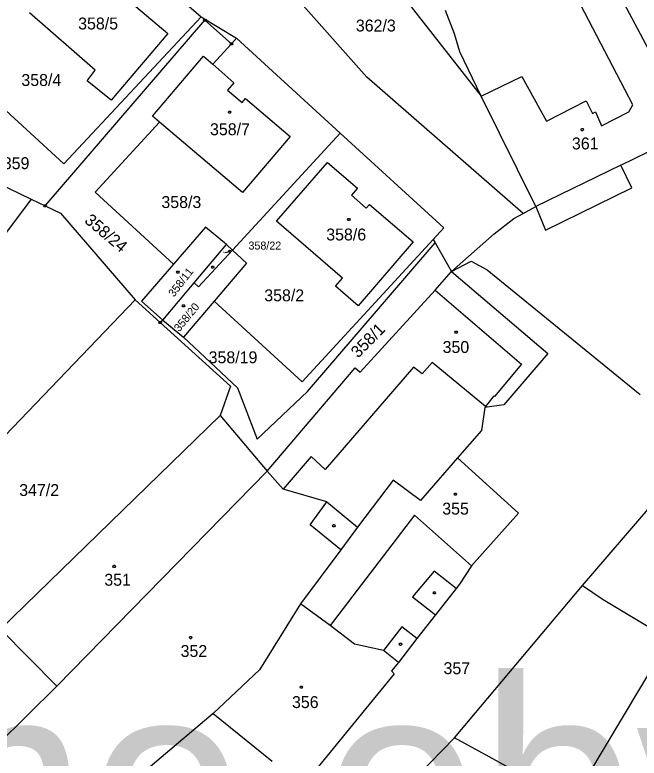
# Model space of a CAD drawing. Extents: x -634640 to -629202, y -1196156 to -1190068.
# Drawn here: x -631895.1 to -631806.2, y -1192622.8 to -1192516.9 of the extents above; entities that cross this region are included whole.
import ezdxf

# ---------------------------------------------------------------- set-up
doc = ezdxf.new("R2010")
doc.units = 0
for name, color, linetype in [('Obvod šetřený', 7, 'Continuous'), ('Vrstva 1', 7, 'Continuous'), ('Vrstva 2', 7, 'Continuous'), ('Vrstva 3', 7, 'Continuous'), ('Vrstva 4', 7, 'Continuous'), ('Vrstva 5', 7, 'Continuous'), ('Vrstva 7', 7, 'Continuous'), ('Vrstva 8', 7, 'Continuous')]:
    doc.layers.add(name, color=color, linetype=linetype)

msp = doc.modelspace()

# ---------------------------------------------------------------- linework, layer by layer
at = {"layer": 'Vrstva 1'}
for p, q in [((-631848.47, -1192503.23), (-631828.68, -1192528.47)), ((-631883.69, -1192504.04), (-631868.59, -1192517.16)), ((-631809.06, -1192513.86), (-631802.3, -1192526.65)), ((-631879.64, -1192514.17), (-631873.34, -1192519.53)), ((-631854.05, -1192515.52), (-631844.97, -1192525.74)), ((-631883.7, -1192524.73), (-631893.04, -1192516.58)), ((-631832.49, -1192519.55), (-631833.8, -1192516.26)), ((-631890.82, -1192544.07), (-631868.06, -1192517.61)), ((-631888.14, -1192538.1), (-631868.59, -1192517.16)), ((-631868.59, -1192517.16), (-631863.55, -1192520.21)), ((-631868.06, -1192517.61), (-631864.27, -1192521)), ((-631873.34, -1192519.53), (-631881.41, -1192529.02)), ((-631864.27, -1192521), (-631863.55, -1192520.21)), ((-631849.92, -1192532.66), (-631863.55, -1192520.21)), ((-631831.75, -1192522.13), (-631832.49, -1192519.55)), ((-631866.95, -1192523.91), (-631864.27, -1192521)), ((-631828.68, -1192528.47), (-631831.75, -1192522.13)), ((-631875.53, -1192531.28), (-631868.28, -1192522.74)), ((-631868.28, -1192522.74), (-631866.95, -1192523.91)), ((-631866.95, -1192523.91), (-631863.93, -1192526.55)), ((-631884.83, -1192526.29), (-631883.7, -1192524.73)), ((-631881.41, -1192529.02), (-631884.83, -1192526.29)), ((-631863.93, -1192526.55), (-631864.82, -1192527.6)), ((-631822.7, -1192545.15), (-631844.97, -1192525.74)), ((-631864.82, -1192527.6), (-631862.75, -1192529.35)), ((-631888.14, -1192538.1), (-631898.97, -1192528.19)), ((-631820.89, -1192544.18), (-631828.68, -1192528.47)), ((-631862.75, -1192529.35), (-631862.27, -1192528.79)), ((-631862.27, -1192528.79), (-631855.91, -1192534.19)), ((-631874.52, -1192532.14), (-631875.53, -1192531.28)), ((-631883.71, -1192542.15), (-631874.52, -1192532.14)), ((-631862.72, -1192542.16), (-631874.52, -1192532.14)), ((-631848.78, -1192533.71), (-631849.92, -1192532.66)), ((-631848.78, -1192533.71), (-631864.13, -1192550.4)), ((-631848.78, -1192533.71), (-631834.02, -1192547.2)), ((-631855.91, -1192534.19), (-631862.72, -1192542.16)), ((-631808.78, -1192538.27), (-631804.91, -1192536.38)), ((-631903.73, -1192537.87), (-631892.82, -1192543.11)), ((-631857.88, -1192546.27), (-631850.61, -1192537.89)), ((-631850.61, -1192537.89), (-631846.32, -1192541.58)), ((-631807.24, -1192541.51), (-631808.78, -1192538.27)), ((-631872.52, -1192552.38), (-631883.71, -1192542.15)), ((-631846.32, -1192541.58), (-631847.19, -1192542.57)), ((-631819.52, -1192547.54), (-631807.24, -1192541.51)), ((-631892.82, -1192543.11), (-631924.11, -1192584.85)), ((-631892.82, -1192543.11), (-631890.82, -1192544.07)), ((-631847.19, -1192542.57), (-631845.08, -1192544.43)), ((-631890.82, -1192544.07), (-631888.62, -1192545.13)), ((-631845.08, -1192544.43), (-631844.61, -1192543.9)), ((-631844.61, -1192543.9), (-631838.38, -1192549.21)), ((-631822.7, -1192545.15), (-631820.89, -1192544.18)), ((-631820.89, -1192544.18), (-631819.52, -1192547.54)), ((-631888.62, -1192545.13), (-631877.99, -1192557.46)), ((-631824.05, -1192545.87), (-631822.7, -1192545.15)), ((-631848.46, -1192554.39), (-631857.88, -1192546.27)), ((-631826.84, -1192548.08), (-631824.05, -1192545.87)), ((-631834.02, -1192547.2), (-631835.55, -1192548.86)), ((-631832.9, -1192553.43), (-631826.84, -1192548.08)), ((-631869.59, -1192555.06), (-631864.98, -1192549.6)), ((-631864.98, -1192549.6), (-631864.13, -1192550.4)), ((-631835.55, -1192548.86), (-631854.19, -1192569.14)), ((-631838.38, -1192549.21), (-631846.23, -1192558.32)), ((-631835.55, -1192548.86), (-631835.27, -1192549.34)), ((-631835.27, -1192549.34), (-631832.9, -1192553.43)), ((-631864.13, -1192550.4), (-631868.95, -1192555.64)), ((-631832.9, -1192553.43), (-631830.13, -1192551.98)), ((-631830.13, -1192551.98), (-631827.83, -1192553.2)), ((-631835.24, -1192556.11), (-631832.9, -1192553.43)), ((-631832.9, -1192553.43), (-631819.2, -1192565.12)), ((-631827.83, -1192553.2), (-631806.05, -1192570.95)), ((-631874.07, -1192560.35), (-631869.59, -1192555.06)), ((-631868.95, -1192555.64), (-631869.59, -1192555.06)), ((-631849.45, -1192555.54), (-631848.46, -1192554.39)), ((-631846.23, -1192558.32), (-631849.45, -1192555.54)), ((-631845.93, -1192567.79), (-631835.24, -1192556.11)), ((-631917.12, -1192598.24), (-631877.99, -1192557.46)), ((-631877.99, -1192557.46), (-631874.44, -1192560.69)), ((-631866.74, -1192557.66), (-631871.11, -1192562.8)), ((-631854.19, -1192569.14), (-631866.74, -1192557.66)), ((-631874.07, -1192560.35), (-631874.44, -1192560.69)), ((-631874.07, -1192560.35), (-631871.11, -1192562.8)), ((-631874.44, -1192560.69), (-631864.43, -1192569.77)), ((-631819.2, -1192565.12), (-631825.47, -1192572.45)), ((-631859.17, -1192581.88), (-631846.63, -1192567.18)), ((-631846.63, -1192567.18), (-631845.93, -1192567.79)), ((-631864.43, -1192569.77), (-631865.89, -1192573.94)), ((-631828.17, -1192572.8), (-631828.64, -1192576.1)), ((-631825.47, -1192572.45), (-631828.17, -1192572.8)), ((-631865.89, -1192573.94), (-631897.2, -1192604.41)), ((-631865.89, -1192573.94), (-631859.17, -1192581.88)), ((-631828.64, -1192576.1), (-631832.09, -1192579.98)), ((-631832.09, -1192579.98), (-631837.33, -1192586.04)), ((-631832.09, -1192579.98), (-631823.36, -1192587.86)), ((-631859.17, -1192581.88), (-631889.18, -1192612.51)), ((-631856.92, -1192584.46), (-631859.17, -1192581.88)), ((-631841.22, -1192583.17), (-631846.32, -1192589.87)), ((-631837.33, -1192586.04), (-631841.22, -1192583.17)), ((-631850.67, -1192586.25), (-631856.92, -1192584.46)), ((-631853.08, -1192589.54), (-631850.67, -1192586.25)), ((-631823.36, -1192587.86), (-631830.08, -1192595.38)), ((-631814.24, -1192598.16), (-631804.61, -1192586.97)), ((-631848.71, -1192593.08), (-631853.08, -1192589.54)), ((-631846.32, -1192589.87), (-631848.71, -1192593.08)), ((-631848.71, -1192593.08), (-631854.42, -1192600.76)), ((-631830.08, -1192595.38), (-631831.79, -1192597.99)), ((-631832.48, -1192619.85), (-631814.24, -1192598.16)), ((-631831.79, -1192597.99), (-631832.27, -1192598.6)), ((-631832.27, -1192598.6), (-631835.2, -1192602.35)), ((-631854.42, -1192600.76), (-631860.29, -1192610.17)), ((-631850.21, -1192603.87), (-631854.42, -1192600.76)), ((-631835.2, -1192602.35), (-631837.85, -1192605.74)), ((-631846.76, -1192606.54), (-631850.21, -1192603.87)), ((-631897.2, -1192604.41), (-631889.18, -1192612.51)), ((-631837.85, -1192605.74), (-631840.49, -1192609.12)), ((-631801.93, -1192605.84), (-631815.78, -1192629)), ((-631842.62, -1192607.45), (-631846.76, -1192606.54)), ((-631840.49, -1192609.12), (-631842.62, -1192607.45)), ((-631840.49, -1192609.12), (-631841.45, -1192610.33)), ((-631860.29, -1192610.17), (-631866.88, -1192616.39)), ((-631841.08, -1192610.76), (-631854.21, -1192626.77)), ((-631841.45, -1192610.33), (-631841.08, -1192610.76)), ((-631889.18, -1192612.51), (-631899.64, -1192622.83)), ((-631866.88, -1192616.39), (-631880.98, -1192628.29)), ((-631866.88, -1192616.39), (-631858.46, -1192623.18)), ((-631851.26, -1192639.1), (-631832.48, -1192619.85)), ((-631815.78, -1192629), (-631832.48, -1192619.85))]:
    msp.add_line(p, q, dxfattribs=at)
for points in [[(-631864.98, -1192549.6), (-631867.96, -1192547.12), (-631872.52, -1192552.38)], [(-631871.11, -1192562.8), (-631863.41, -1192570.03), (-631860.61, -1192577.31), (-631853.46, -1192570.55), (-631835.27, -1192549.34)], [(-631864.13, -1192550.4), (-631862.14, -1192552.25), (-631866.74, -1192557.66)], [(-631872.52, -1192552.38), (-631877.08, -1192557.66), (-631874.07, -1192560.35)]]:
    msp.add_lwpolyline(points, dxfattribs=at)
at = {"layer": 'Vrstva 3'}
for points in [[(-631880.91, -1192595.29), (-631880.82, -1192595.44), (-631880.91, -1192595.59), (-631881.09, -1192595.59), (-631881.18, -1192595.44), (-631881.09, -1192595.29), (-631880.91, -1192595.29)], [(-631870, -1192605.45), (-631869.91, -1192605.6), (-631870, -1192605.75), (-631870.18, -1192605.75), (-631870.27, -1192605.6), (-631870.18, -1192605.45), (-631870, -1192605.45)], [(-631854.24, -1192612.5), (-631854.15, -1192612.65), (-631854.24, -1192612.8), (-631854.42, -1192612.8), (-631854.51, -1192612.65), (-631854.42, -1192612.5), (-631854.24, -1192612.5)]]:
    msp.add_lwpolyline(points, dxfattribs=at)
at = {"layer": 'Vrstva 4'}
for p, q in [((-631807.1, -1192529.67), (-631822.2, -1192500.63)), ((-631828.68, -1192528.47), (-631822.89, -1192525.66)), ((-631822.89, -1192525.66), (-631819.41, -1192532.02)), ((-631819.41, -1192532.02), (-631813.73, -1192529.12)), ((-631813.73, -1192529.12), (-631812.83, -1192530.92)), ((-631807.64, -1192530.68), (-631807.1, -1192529.67)), ((-631812.83, -1192530.92), (-631812.4, -1192530.69)), ((-631812.4, -1192530.69), (-631811.53, -1192532.7)), ((-631811.53, -1192532.7), (-631807.64, -1192530.68)), ((-631808.78, -1192538.27), (-631820.89, -1192544.18)), ((-631835.24, -1192556.11), (-631822.95, -1192566.65)), ((-631835.7, -1192566.41), (-631837.1, -1192568)), ((-631828.07, -1192572.67), (-631835.7, -1192566.41)), ((-631822.95, -1192566.65), (-631826.78, -1192571.23)), ((-631838.34, -1192567.04), (-631850.91, -1192581.65)), ((-631837.1, -1192568), (-631838.34, -1192567.04)), ((-631826.89, -1192571.15), (-631828.07, -1192572.67)), ((-631826.78, -1192571.23), (-631826.89, -1192571.15)), ((-631852.93, -1192579.8), (-631856.92, -1192584.46)), ((-631850.91, -1192581.65), (-631852.93, -1192579.8)), ((-631850.67, -1192586.25), (-631846.32, -1192589.87)), ((-631838.2, -1192588.17), (-631850.21, -1192603.87)), ((-631830.08, -1192595.38), (-631838.2, -1192588.17)), ((-631835.41, -1192596.12), (-631838.46, -1192599.78)), ((-631832.27, -1192598.6), (-631835.41, -1192596.12)), ((-631814.24, -1192598.16), (-631811.3, -1192600.18)), ((-631838.46, -1192599.78), (-631835.2, -1192602.35)), ((-631811.3, -1192600.18), (-631804.41, -1192604.31)), ((-631839.98, -1192604.05), (-631842.62, -1192607.45)), ((-631837.85, -1192605.74), (-631839.98, -1192604.05))]:
    msp.add_line(p, q, dxfattribs=at)
at = {"layer": 'Vrstva 5'}
for points in [[(-631864.45, -1192530.57), (-631864.36, -1192530.72), (-631864.45, -1192530.87), (-631864.63, -1192530.87), (-631864.72, -1192530.72), (-631864.63, -1192530.57), (-631864.45, -1192530.57)], [(-631814.2, -1192533.07), (-631814.11, -1192533.22), (-631814.2, -1192533.37), (-631814.38, -1192533.37), (-631814.47, -1192533.22), (-631814.38, -1192533.07), (-631814.2, -1192533.07)], [(-631847.46, -1192545.89), (-631847.37, -1192546.04), (-631847.46, -1192546.19), (-631847.64, -1192546.19), (-631847.73, -1192546.04), (-631847.64, -1192545.89), (-631847.46, -1192545.89)], [(-631866.86, -1192552.65), (-631866.77, -1192552.8), (-631866.86, -1192552.95), (-631867.04, -1192552.95), (-631867.13, -1192552.8), (-631867.04, -1192552.65), (-631866.86, -1192552.65)], [(-631871.84, -1192553.39), (-631871.75, -1192553.54), (-631871.84, -1192553.69), (-631872.02, -1192553.69), (-631872.11, -1192553.54), (-631872.02, -1192553.39), (-631871.84, -1192553.39)], [(-631871.03, -1192558.17), (-631870.94, -1192558.32), (-631871.03, -1192558.47), (-631871.21, -1192558.47), (-631871.3, -1192558.32), (-631871.21, -1192558.17), (-631871.03, -1192558.17)], [(-631832.16, -1192561.92), (-631832.07, -1192562.07), (-631832.16, -1192562.22), (-631832.34, -1192562.22), (-631832.43, -1192562.07), (-631832.34, -1192561.92), (-631832.16, -1192561.92)], [(-631832.29, -1192585.02), (-631832.2, -1192585.17), (-631832.29, -1192585.32), (-631832.47, -1192585.32), (-631832.56, -1192585.17), (-631832.47, -1192585.02), (-631832.29, -1192585.02)], [(-631849.59, -1192589.5), (-631849.5, -1192589.65), (-631849.59, -1192589.8), (-631849.77, -1192589.8), (-631849.86, -1192589.65), (-631849.77, -1192589.5), (-631849.59, -1192589.5)], [(-631835.28, -1192599.07), (-631835.19, -1192599.22), (-631835.28, -1192599.37), (-631835.46, -1192599.37), (-631835.55, -1192599.22), (-631835.46, -1192599.07), (-631835.28, -1192599.07)], [(-631840.09, -1192606.4), (-631840, -1192606.55), (-631840.09, -1192606.7), (-631840.27, -1192606.7), (-631840.36, -1192606.55), (-631840.27, -1192606.4), (-631840.09, -1192606.4)]]:
    msp.add_lwpolyline(points, dxfattribs=at)
at = {"layer": 'Vrstva 7'}
msp.add_line((-631865.21, -1192550.73), (-631864.52, -1192550.56), dxfattribs=at)
msp.add_lwpolyline([(-631864.353, -1192550.611), (-631864.477, -1192550.735), (-631864.644, -1192550.683), (-631864.687, -1192550.509), (-631864.563, -1192550.385), (-631864.396, -1192550.437), (-631864.353, -1192550.611)], dxfattribs=at)
at = {"layer": 'Vrstva 8'}
for points in [[(-631867.97, -1192517.46), (-631867.88, -1192517.61), (-631867.97, -1192517.76), (-631868.15, -1192517.76), (-631868.24, -1192517.61), (-631868.15, -1192517.46), (-631867.97, -1192517.46)], [(-631864.18, -1192520.85), (-631864.09, -1192521), (-631864.18, -1192521.15), (-631864.36, -1192521.15), (-631864.45, -1192521), (-631864.36, -1192520.85), (-631864.18, -1192520.85)], [(-631890.73, -1192543.92), (-631890.64, -1192544.07), (-631890.73, -1192544.22), (-631890.91, -1192544.22), (-631891, -1192544.07), (-631890.91, -1192543.92), (-631890.73, -1192543.92)], [(-631874.35, -1192560.54), (-631874.26, -1192560.69), (-631874.35, -1192560.84), (-631874.53, -1192560.84), (-631874.62, -1192560.69), (-631874.53, -1192560.54), (-631874.35, -1192560.54)]]:
    msp.add_lwpolyline(points, dxfattribs=at)

# ---------------------------------------------------------------- texts
at = {"layer": 'Obvod šetřený'}
msp.add_text('mimo obvod KoPÚ', height=30, dxfattribs=at).set_placement((-631960.455, -1192641.53))
at = {"layer": 'Vrstva 2'}
for s, height, p in [('358/5', 1.7, (-631886.123, -1192518.95)), ('362/3', 1.7, (-631846.553, -1192519.24)), ('358/4', 1.7, (-631894.213, -1192527)), ('358/7', 1.7, (-631867.333, -1192534.02)), ('361', 1.7, (-631815.763, -1192536.04)), ('359', 1.7, (-631896.859, -1192538.85)), ('358/3', 1.7, (-631874.263, -1192544.39)), ('358/6', 1.7, (-631850.773, -1192549.01)), ('358/22', 0.1, (-631865.49, -1192550.73)), ('358/2', 1.7, (-631859.603, -1192557.68)), ('350', 1.7, (-631834.193, -1192565.04)), ('358/19', 1.7, (-631867.53, -1192566.51)), ('347/2', 1.7, (-631894.523, -1192585.42)), ('355', 1.7, (-631834.243, -1192588.07)), ('351', 1.7, (-631882.393, -1192598.2)), ('352', 1.7, (-631871.523, -1192608.35)), ('357', 1.7, (-631834.063, -1192610.8)), ('356', 1.7, (-631855.653, -1192615.63))]:
    msp.add_text(s, height=height, dxfattribs=at).set_placement(p)
for s, height, rotation, p in [('358/24', 1.7, 319.88234, (-631885.34, -1192546.358)), ('358/11', 1.14, 52.42564, (-631872.475, -1192557.158)), ('358/20', 1.14, 50.70676, (-631871.708, -1192562.106)), ('358/1', 1.7, 45.43555, (-631846.233, -1192565.851))]:
    msp.add_text(s, height=height, rotation=rotation, dxfattribs=at).set_placement(p)
at = {"layer": 'Vrstva 7'}
msp.add_text('358/22', height=1.14, dxfattribs=at).set_placement((-631861.851, -1192550.31))

doc.saveas('drawing.dxf')
